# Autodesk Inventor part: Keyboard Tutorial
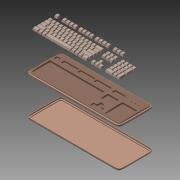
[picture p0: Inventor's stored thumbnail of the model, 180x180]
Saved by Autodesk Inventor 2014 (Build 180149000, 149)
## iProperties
Created: 2008-10
Part Number: Keyboard Tutorial
Document SubType Name: Modeling
Designer: floress
Density: 1 g/cm^3
Mass: 799.231 g
Surface Area: 6344.35 cm^2
Volume: 799.231 cm^3
Material: Generic
Appearance: Default
Author: floress
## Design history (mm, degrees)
node "Keyboard.wire"
feature "Stitch Surface1"
feature "Sculpt1"
shell "Shell1" dims "d1" = 1.9
split "Split1"
  body "Solid1"
feature "Sculpt3"
feature "Move Body3"
feature "Move Body4"
feature "Stitch Surface2"
body "Srf29"
feature "Stitch Surface3"
body "Srf30"
feature "Stitch Surface4"
body "Srf31"
feature "Stitch Surface5"
body "Srf32"
feature "Stitch Surface6"
body "Srf33"
feature "Stitch Surface7"
body "Srf34"
feature "Stitch Surface8"
body "Srf35"
feature "Stitch Surface9"
body "Srf36"
feature "Stitch Surface10"
body "Srf37"
feature "Stitch Surface11"
body "Srf38"
feature "Stitch Surface12"
body "Srf39"
feature "Stitch Surface13"
body "Srf40"
node "Buttons"
feature "Keys"
body "Srf1"
feature "Cavity_3_Bottom"
body "Srf2"
feature "Cavity_6_Sides"
body "Srf3"
feature "Cavity_8_Bottom"
body "Srf4"
feature "LED_2_Bottom"
body "Srf5"
feature "Cavity_5_Sides"
body "Srf6"
feature "LED_3_Sides"
body "Srf7"
feature "Cavity_5_Bottom"
body "Srf8"
feature "Cavity_1_Bottom"
body "Srf9"
feature "Cavity_7_Bottom"
body "Srf10"
feature "Cavity_9_Sides"
body "Srf11"
feature "LED_1_Sides"
body "Srf12"
feature "Cavity_9_Bottom"
body "Srf13"
feature "Cavity_3_Sides"
body "Srf14"
feature "Cavity_4_Bottom"
body "Srf15"
feature "Cavity_4_Sides"
body "Srf16"
feature "LED_2_Sides"
body "Srf17"
feature "Cavity_7_Sides"
body "Srf18"
feature "LED_3_Bottom"
body "Srf19"
feature "Cavity_2_Sides"
body "Srf20"
feature "Cavity_1_Sides"
body "Srf21"
feature "Cavity_6_Bottom"
body "Srf22"
feature "Cavity_2_Bottom"
body "Srf23"
feature "Split_Tool"
body "Srf24"
feature "Cavity_8_Sides"
body "Srf25"
feature "LED_1_Bottom"
body "Srf26"
feature "Body"
body "Srf27"
feature "Logo"
body "Srf28"
node "Top"
node "Bottom"
other parameters: "d45" = 0, "d47" = 0, "d48" = 0, "d50" = 0
